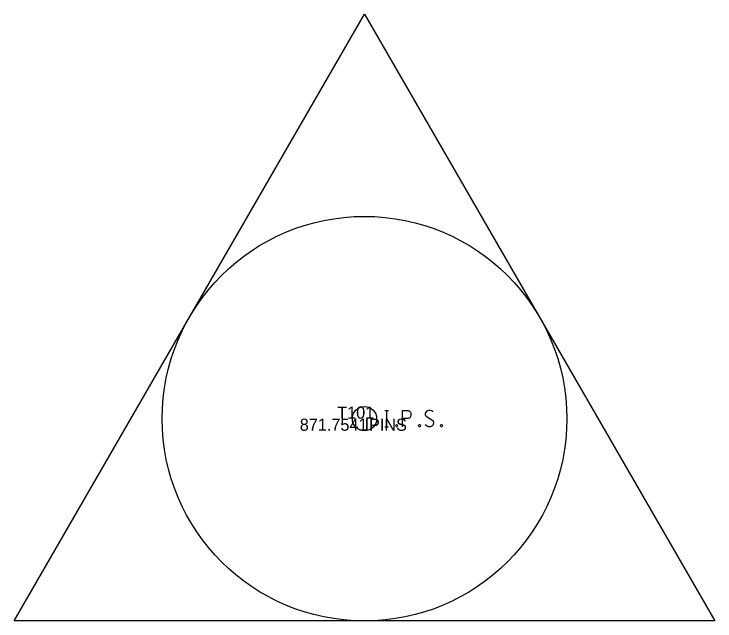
# Model space of a CAD drawing. Extents: x 1479425 to 1480294, y 379351 to 380102.
# Drawn here: x 1480059.101 to 1480062.565, y 379498.092 to 379501.092 of the extents above; entities that cross this region are included whole.
import ezdxf

# ---------------------------------------------------------------- set-up
doc = ezdxf.new("R2010")
doc.units = 0
for name, color, linetype in [('SV_Control_Point', 7, 'Continuous'), ('SV_P_Mon_Cells_Set', 7, 'Continuous'), ('SV_X_Text_Comment', 7, 'Continuous'), ('SV_X_Text_Elevation', 7, 'Continuous'), ('SV_X_Text_Name', 7, 'Continuous')]:
    doc.layers.add(name, color=color, linetype=linetype)

msp = doc.modelspace()

# ---------------------------------------------------------------- linework, layer by layer
at = {"layer": 'SV_Control_Point'}
for p, q in [((1480059.1009, 379498.0924), (1480060.833, 379501.0924)), ((1480060.833, 379501.0924), (1480062.565, 379498.0924)), ((1480060.833, 379499.0924), (1480060.833, 379499.0924)), ((1480062.565, 379498.0924), (1480059.1009, 379498.0924))]:
    msp.add_line(p, q, dxfattribs=at)
msp.add_circle((1480060.833, 379499.0924), 1, dxfattribs=at)
at = {"layer": 'SV_P_Mon_Cells_Set'}
for points in [[(1480060.9339, 379499.1325), (1480060.9516, 379499.1325)], [(1480060.9428, 379499.0525), (1480060.9428, 379499.1325)], [(1480061.021, 379499.0525), (1480061.021, 379499.1325), (1480061.0475, 379499.1325), (1480061.0502, 379499.1319), (1480061.0541, 379499.1306), (1480061.0558, 379499.1293), (1480061.0574, 379499.1281), (1480061.0596, 379499.1249), (1480061.0613, 379499.1218), (1480061.0624, 379499.1168), (1480061.0624, 379499.1092), (1480061.0618, 379499.1067), (1480061.0607, 379499.1029), (1480061.0585, 379499.0985), (1480061.0563, 379499.0966), (1480061.0547, 379499.0953), (1480061.0519, 379499.0941), (1480061.0475, 379499.0935), (1480061.021, 379499.0935)], [(1480061.1715, 379499.1268), (1480061.1704, 379499.1281), (1480061.1687, 379499.1293), (1480061.1638, 379499.1312), (1480061.1577, 379499.1325), (1480061.1533, 379499.1325), (1480061.1517, 379499.1325), (1480061.1445, 379499.1306), (1480061.1384, 379499.1268), (1480061.1346, 379499.1218), (1480061.1335, 379499.1168), (1480061.1335, 379499.113), (1480061.1346, 379499.1079), (1480061.139, 379499.1035), (1480061.1693, 379499.0846), (1480061.172, 379499.0821), (1480061.1731, 379499.0796), (1480061.1742, 379499.0758), (1480061.1742, 379499.072), (1480061.1737, 379499.0683), (1480061.1731, 379499.0657), (1480061.172, 379499.0626), (1480061.1709, 379499.0601), (1480061.1698, 379499.0582), (1480061.1682, 379499.0563), (1480061.1665, 379499.055), (1480061.1643, 379499.0538), (1480061.1627, 379499.0531), (1480061.1577, 379499.0525), (1480061.15, 379499.0525), (1480061.145, 379499.0538), (1480061.1379, 379499.0582), (1480061.1335, 379499.062)], [(1480060.9339, 379499.0525), (1480060.9516, 379499.0525)], [(1480060.9907, 379499.0632), (1480060.9935, 379499.0632), (1480060.9951, 379499.062), (1480060.9968, 379499.0594), (1480060.9968, 379499.0563), (1480060.9951, 379499.0538), (1480060.9935, 379499.0525), (1480060.9907, 379499.0525), (1480060.9891, 379499.0538), (1480060.9874, 379499.0563), (1480060.9874, 379499.0594), (1480060.9891, 379499.062), (1480060.9907, 379499.0632)], [(1480061.1032, 379499.0632), (1480061.1059, 379499.0632), (1480061.1076, 379499.062), (1480061.1092, 379499.0594), (1480061.1092, 379499.0563), (1480061.1076, 379499.0538), (1480061.1059, 379499.0525), (1480061.1032, 379499.0525), (1480061.1015, 379499.0538), (1480061.0998, 379499.0563), (1480061.0998, 379499.0594), (1480061.1015, 379499.062), (1480061.1032, 379499.0632)], [(1480061.2123, 379499.0632), (1480061.215, 379499.0632), (1480061.2167, 379499.062), (1480061.2183, 379499.0594), (1480061.2183, 379499.0563), (1480061.2167, 379499.0538), (1480061.215, 379499.0525), (1480061.2123, 379499.0525), (1480061.2106, 379499.0538), (1480061.209, 379499.0563), (1480061.209, 379499.0594), (1480061.2106, 379499.062), (1480061.2123, 379499.0632)]]:
    msp.add_lwpolyline(points, dxfattribs=at)
msp.add_circle((1480060.833, 379499.0924), 0.06, dxfattribs=at)

# ---------------------------------------------------------------- texts
at = {"layer": 'SV_X_Text_Comment'}
msp.add_text('IPINS', height=0.06, dxfattribs=at).set_placement((1480060.833, 379499.0324))
at = {"layer": 'SV_X_Text_Elevation'}
msp.add_text('871.7541', height=0.06, dxfattribs=at).set_placement((1480060.513, 379499.0324))
at = {"layer": 'SV_X_Text_Name'}
msp.add_text('T101', height=0.06, dxfattribs=at).set_placement((1480060.6982, 379499.0924))

doc.saveas('drawing.dxf')
